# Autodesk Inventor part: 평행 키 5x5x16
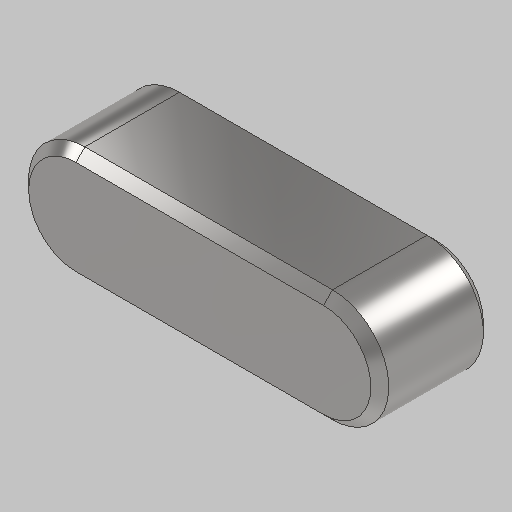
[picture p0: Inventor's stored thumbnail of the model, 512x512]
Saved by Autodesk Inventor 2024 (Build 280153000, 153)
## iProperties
Created: 2026-01
Part Number: 평행 키 5x5x16
Material: 강철, 연강
Description: 키 및 해당 키홈
Document SubType Name: Modeling
Designer: 2-10
Density: 7.85 g/cm^3
Appearance: 기본값
Author: jhkim
Sending System: Autodesk Inventor 2026
Preprocessor: ST-DEVELOPER v20.1
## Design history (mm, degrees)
feature "Solid1"
node "솔리드1"
